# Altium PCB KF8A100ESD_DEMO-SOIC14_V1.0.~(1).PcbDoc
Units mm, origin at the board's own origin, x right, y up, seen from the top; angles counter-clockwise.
Board outline 54 x 31.99 mm, 2 copper layers (Top Layer, Bottom Layer); 38 components, 27 nets, 94 pads, 10 vias.
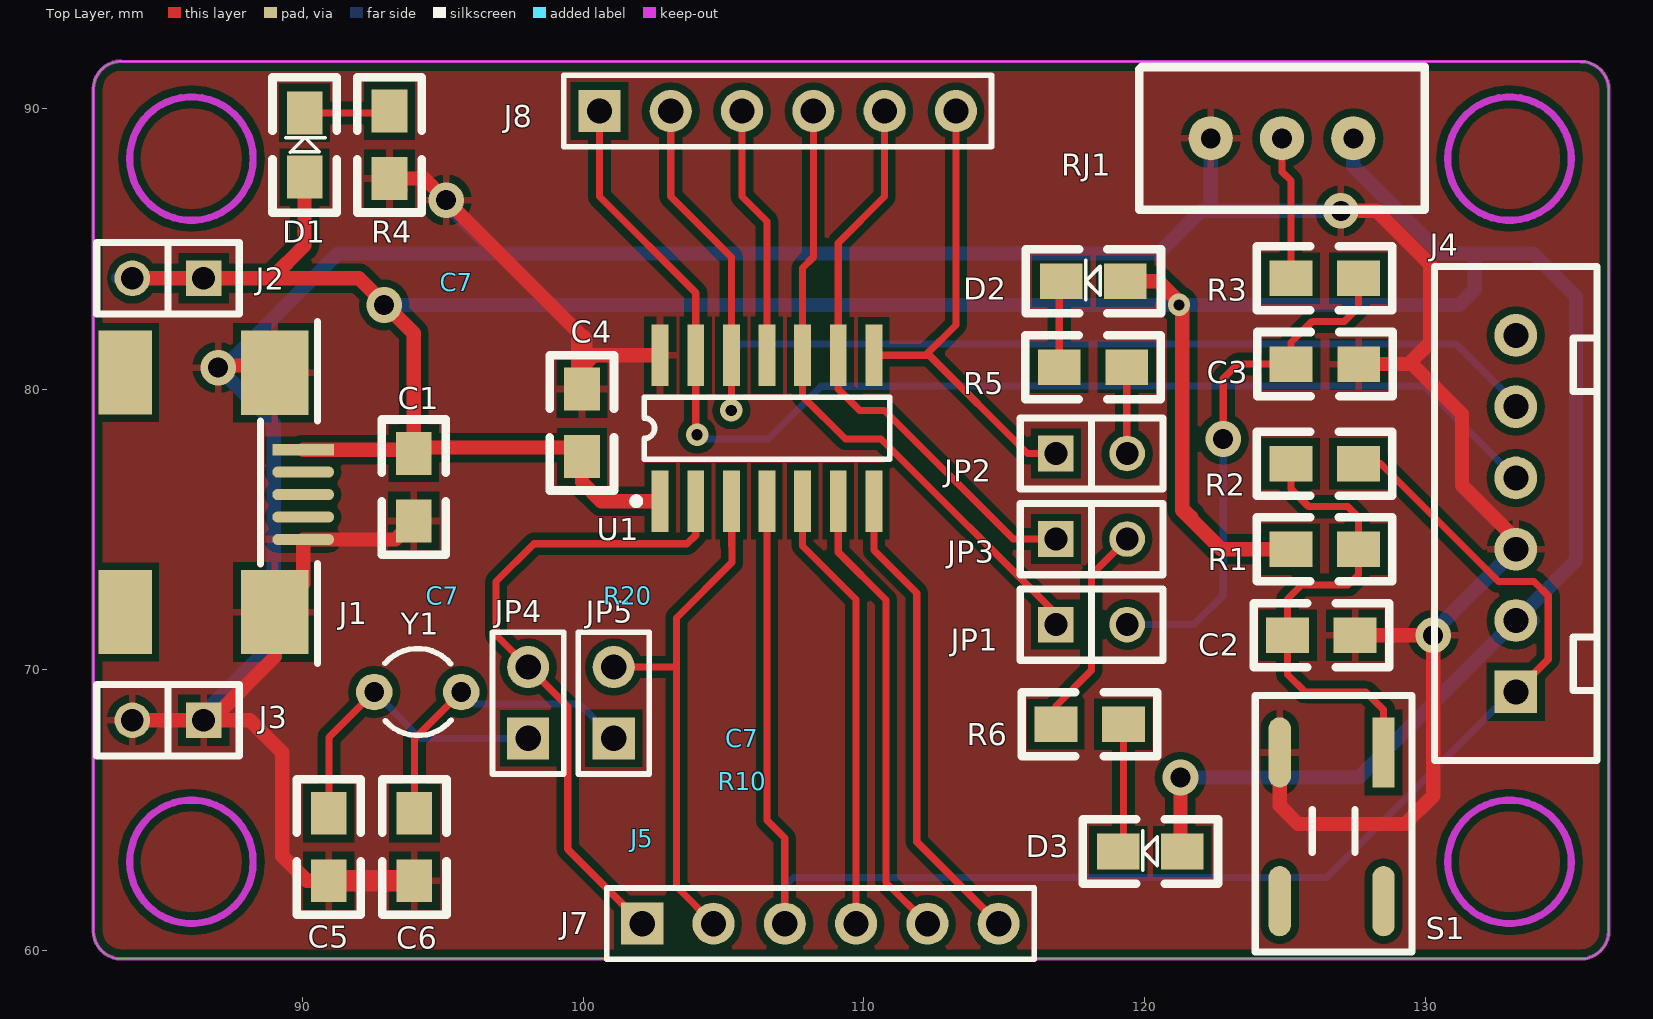
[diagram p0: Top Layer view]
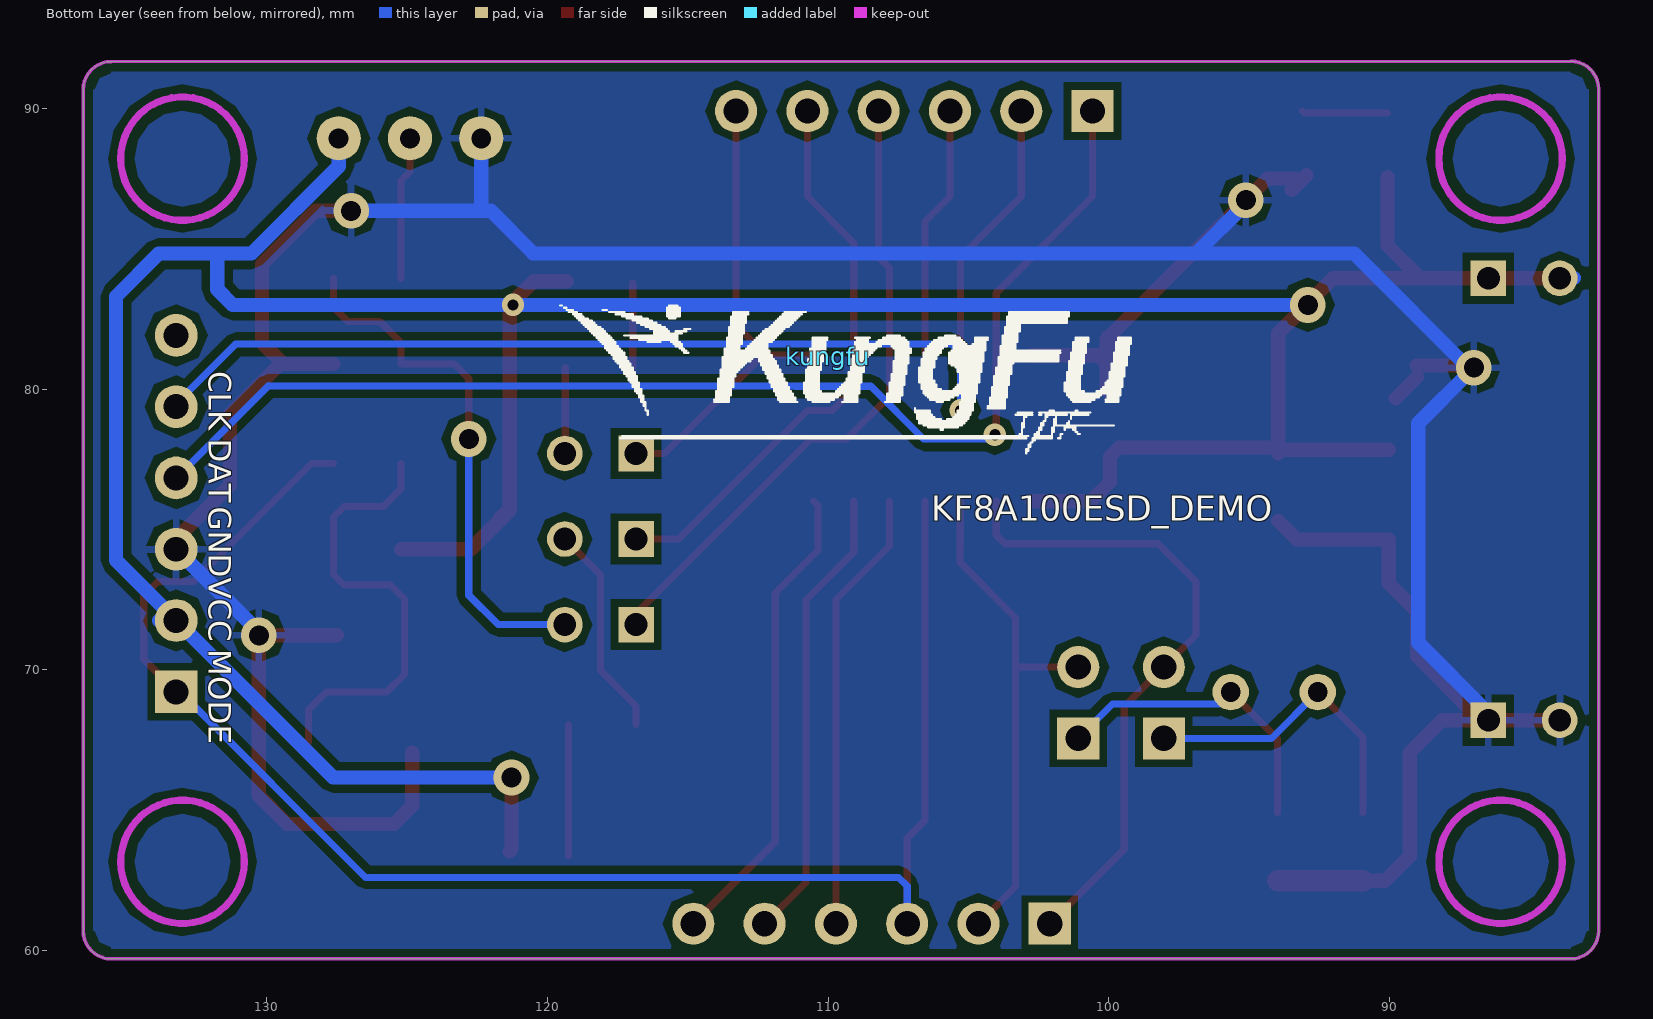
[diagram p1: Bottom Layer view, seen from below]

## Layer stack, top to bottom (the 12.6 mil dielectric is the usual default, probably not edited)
Top Solder: solder mask 0.0102, Solder Resist, Dk 3.5
Top Layer: signal copper 0.0356
Dielectric1: dielectric 0.32, FR-4, Dk 4.8
Bottom Layer: signal copper 0.0356
Bottom Solder: solder mask 0.0102, Solder Resist, Dk 3.5

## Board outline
82.55,60.706 ccw(c83.55,60.706) 83.55,59.706 135.55,59.706 ccw(c135.55,60.706) 136.55,60.706 136.55,90.678 ccw(c135.55,90.678) 135.55,91.678 83.55,91.694 ccw(c83.55,90.694) 82.55,90.694

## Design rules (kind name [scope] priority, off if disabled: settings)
Clearance [All] p1: gap=0.27
ComponentClearance [All] p1: gap=0 collisioncheckmode=3 verticalgap=0.254 showdistances=FALSE
FabricationTestPointUsage TestPointUsage [All] p1: valid=0 allowmultiple=FALSE
FabricationTestpoint Testpoint [All] p1: side=3 testpointundercomponent=TRUE minsize=1.016 maxsize=2.54 preferedsize=1.524 minholesize=0 maxholesize=1.016 preferedholesize=0.813 testpointgrid=0.025 allowsidetop=TRUE allowsidebottom=TRUE usegrid=TRUE gridtolerance=0
PolygonConnect [All] p1: connectstyle=Relief reliefconductorwidth=0.254 reliefentries=4 polygonreliefangle="90 Angle" airgapwidth=0.254
RoutingVias [All] p1: holewidth=0.711 width=1.27 viastyle="Through Hole" minholewidth=0.3 minwidth=0.6 maxholewidth=0.711 maxwidth=1.5
SilkToSolderMaskClearance SilkscreenOverComponentPads [IsPad] p1: minsilkscreentomaskgap=0.254 clearancetoexposedcopper=TRUE
SolderMaskExpansion [All] p1: expansion=0.102
UnpouredPolygon [All] p1: allowunpoured=FALSE
Width [InNet('GND')or InNet('VCC')] p1: maxlimit=0.762 minlimit=0.254 preferedwidth=0.254
25 further rules are at their usual default settings.

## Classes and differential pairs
component class KF8F3130-SOIC14: C1 C2 C3 C4 C5 C6 C7 D1 D2 J1 J2 J3 J4 J5 J6 J7 J8 JP1 JP2 JP3 JP4 JP5 R1 R2 R3 R4 R5 R6 RJ1 S1 U1 Y1

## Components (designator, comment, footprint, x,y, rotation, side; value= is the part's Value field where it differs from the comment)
C1 "105" 0805#1 93.98,77.724 r270 top
C2 "105" 0805#1 125.095,71.247 r0 top
C3 "103" 0805#1 125.221,80.909 r0 top
C4 "104" 0805#1 99.949,77.597 r90 top
C5 "" 0805#1 90.932,62.484 r90 top
C6 "" 0805#1 93.98,62.484 r90 top
C7 "Comment" 0603 105.664,67.564 r180 top
C7 "Comment" 0805#2 94.996,72.644 r180 top
C7 "105" 0805#2 95.504,83.82 r0 top
D1 "LED" LED0805 90.043,87.503 r90 top
D2 "LED" LED0805 119.38,83.82 r180 top
D3 "LED" LED0805 121.412,63.5 r180 top
J1 "Mini-IN" "MINI B USB" 90.035,74.653 r90 top
J2 "CON2" SIP2 86.487,83.947 r180 top
J3 "CON2" SIP2 86.487,68.199 r180 top
J4 "CON6" ICSP887 133.223,69.215 r90 top
J5 "Header 6" HDR1X6#1 102.108,64.008 r0 top
J6 "Header 6" HDR1X6#1 100.584,86.868 r0 top
J7 "Header 6" HDR1X6#2 102.108,60.96 r0 top
J8 "Header 6" HDR1X6#2 100.584,89.916 r0 top
JP1 "CON1X2" SIP2 116.84,71.628 r0 top
JP2 "CON1X2" SIP2 116.84,77.724 r0 top
JP3 "CON1X2" SIP2 116.84,74.676 r0 top
JP4 "" HDR1X3 98.044,67.564 r90 top
JP5 "" HDR1X3 101.092,67.564 r90 top
kungfu "Comment" KUNGFU 110.007,81.178 r180 bottom locked
R1 "30K" 0805#1 127.635,74.295 r180 top
R2 "1k" 0805#1 127.635,77.343 r180 top
R3 "1K" 0805#1 127.635,83.947 r180 top
R4 "330" 0805#1 93.091,87.503 r90 top
R5 "330" 0805#1 119.38,80.772 r180 top
R6 "330" 0805#1 116.84,68.072 r0 top
R10 "Comment" 0603 105.664,66.04 r180 top
R20 "Comment" 0805#2 101.6,72.644 r180 top
RJ1 "10K" VR5H 127.508,88.9 r180 top
S1 "" SW_SOP 128.524,67.056 r270 top
U1 "KF8F3132-SOIC20" SO14 106.553,78.613 r0 top
Y1 "32.768kHz" BCY-W2/D3.1 94.107,69.215 r90 top

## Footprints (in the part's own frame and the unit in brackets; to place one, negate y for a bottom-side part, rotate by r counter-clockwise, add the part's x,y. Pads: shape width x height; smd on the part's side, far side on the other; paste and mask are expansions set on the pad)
0603 [mm] "Chip Capacitor; Body 1.6 x 0.8 mm (LxW typ)"
0805#1 [mil]
  rect 60x50 smd: 1(0.31,-0.41) 2(95.03,-0.41)
  silkscreen extent -47,-45 143,45
0805#2 [mil]
BCY-W2/D3.1 [mm] "Crystal, Thru-Hole; 2 Leads; Body 3.1 x 8.2 mm (Dia.xH)"
  round 1.3 hole 0.7: 1(0,1.55) 2(0,-1.55)
  silkscreen extent -1.55,-1.19 1.55,1.17
HDR1X3 [mm] "Connector; Header; 3 Position"
  rect 1.5x1.5 hole 0.9: 1(0,0)
  round 1.5 hole 0.9: 2(2.54,0)
  silkscreen extent -1.27,-1.27 3.78,1.27
HDR1X6#1 [mm] "Connector; Header; 6 Position"
HDR1X6#2 [mm] "Connector; Header; 6 Position"
  rect 1.5x1.5 hole 0.9: 1(0,0)
  round 1.5 hole 0.9: 2(2.54,0) 3(5.08,0) 4(7.62,0) 5(10.16,0) 6(12.7,0)
  silkscreen extent -1.27,-1.27 13.97,1.27
ICSP887 [mil]
  rect 60x60 hole 35: 1(0.31,-0.41)
  round 60 hole 35: 2(100.31,-0.41) 3(200.31,-0.41) 4(300.31,-0.41) 5(400.31,-0.41) 6(500.31,-0.41)
  silkscreen extent -96,-115 597,114
KUNGFU [mm]
  silkscreen extent -9.55,-3.45 10.79,1.8
LED0805 [mil]
  rect 60x50 smd: A(2.31,-1.34) K(92.31,-1.34)
  silkscreen extent -48,-46 142,44
"MINI B USB" [mm]
  oval 0.4x2.2 smd: 1(-0.002,0.008) 2(0.798,0.008) 3(1.598,0.008) 4(2.398,0.008)
  rect 0.4x2.2 smd: 5(3.198,0.008)
  rect 3x2.4 smd: A1(-2.59,1.024) A1(5.938,1.024)
  rect 3x1.9 smd: A1(-2.587,6.348) A1(5.947,6.348)
  silkscreen extent -4.42,-0.5 7.77,1.53
SIP2 [mil]
  rect 50x50 hole 32: 1(0.31,-0.41)
  round 50 hole 32: 2(100.31,-0.41)
  silkscreen extent -50,-50 150,50
SO14 [mm] "Small Outline; 14 Leads; Body Width 3.9 mm; Pitch 1.27 mm"
  rect 0.6x2.2 smd: 1(-3.81,-2.6) 2(-2.54,-2.6) 3(-1.27,-2.6) 4(0,-2.6) 5(1.27,-2.6) 6(2.54,-2.6) 7(3.81,-2.6) 8(3.81,2.6) 9(2.54,2.6) 10(1.27,2.6) 11(0,2.6) 12(-1.27,2.6) 13(-2.54,2.6) 14(-3.81,2.6)
  silkscreen extent -4.78,-2.72 4.37,1.1
SW_SOP [mm]
  rect 2.5x0.8 smd: 1(-0.006,-0.003)
  oval 2.5x0.8 smd: 2(-0.006,-3.703) 3(5.294,-3.703) 4(5.294,-0.003)
  silkscreen extent -2.04,-4.57 7.11,1.01
VR5H [mil]
  round 62 hole 28: 1(2.5,-1.8) 2(202.5,-1.8) 3(102.5,-1.8)
  silkscreen extent -97,-102 303,98

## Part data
C1 C2 C3 C4 C5 C6 C7: library part CAP, "Capacitor"
J1: library part USB-5, "USB 1.1, Right Angle, Thru-Hole, Reverse Type, Receptacle, 4 Position, Black"
J2 J3 J4: "Connector"
J5 J7: library part "Header 9", "Header, 9-Pin"
J6 J8: "Header, 6-Pin"
JP1 JP2 JP3: "J?"
JP4 JP5: library part "Header 3", "Header, 3-Pin"
R1 R2 R3 R4 R5 R6: library part RES2
RJ1: library part POT2, "Potentiometer"
S1: library part KEY_X
U1: library part KF8F3130-SOIC14
Y1: library part XTAL, "Crystal Oscillator"

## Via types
v1: diameter 1.27, hole 0.711, Top Layer to Bottom Layer, tented both sides, 7 vias
v2: diameter 0.8, hole 0.4, Top Layer to Bottom Layer, tented both sides, 3 vias

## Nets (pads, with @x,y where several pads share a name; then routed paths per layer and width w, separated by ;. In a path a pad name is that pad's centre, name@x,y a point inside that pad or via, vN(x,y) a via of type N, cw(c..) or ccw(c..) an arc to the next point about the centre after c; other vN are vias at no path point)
GND: C1.2 C2.2 C3.2 C4.2 C5.1 C6.1 J1.1 J1.A1@89.01,72.063 J1.A1@89.01,80.591 J3.1 J3.2 J4.3 R4.1 RJ1.2 S1.2 U1.14 | length 145.8
  Top Layer w0.508: J3.2@83.703,68.209 88.128,68.209 89.281,67.056 89.281,63.373 90.162,62.492 C5.1 ; J3.1@86.751,68.209 89.019,70.477 J1.A1@89.019,71.913 ; v1(86.995,80.772) 87.071,80.848 J1.A1@89.027,80.848 ; J1.A1@89.01,72.063 90.026,73.079 J1.1 93.31,74.651 C1.2 ; J1.A1@89.019,80.441 J1.A1@89.789,79.671 ; R4.1@92.964,87.63 R4.1@93.482,87.112 ; R4.1@93.353,87.511 94.353,87.511 100,81.864 ; C4.2 99.959,80.782 100.39,81.213 U1.14 ; S1.2 124.821,65.171 125.476,64.516 129.286,64.516 130.292,65.522 v1(130.292,71.237) C2.2 ; v1(127,86.36) 128.27,86.36 130.175,84.455 130.175,81.661 129.413,80.899 ; C3.2 129.54,80.899 131.318,79.121 131.318,76.581 133.233,74.666 J4.3
  Top Layer w0.762: C5.1 C6.1 ; C4.2 99.959,81.768
  Bottom Layer w0.508: J3.1 86.479,68.471 88.976,70.968 88.976,78.791 v1@87.097,80.67 ; v1@86.817,80.62 87.046,80.62 91.262,84.836 120.523,84.836 120.523,84.861 122.022,86.36 v1(127,86.36) ; v1(95.123,86.741) 95.123,86.614 96.901,84.836 ; 122.364,86.36 RJ1.2 ; v1(130.292,71.237) 130.292,71.361 J4.3
NetC2_1: C2.1 R1.1 R2.2 S1.1 | length 16.4
  Top Layer w0.254: R2.2 125.221,76.455 125.857,75.819 127.254,75.819 127.627,75.446 127.627,73.398 127.254,73.025 125.603,73.025 125.103,72.525 125.103,69.842 125.73,69.215 127.889,69.215 128.521,68.583 S1.1@128.521,67.44
NetC3_1: C3.1 JP1.2 R3.1 | length 19
  Top Layer w0.254: v1(122.809,78.232) 122.809,80.391 123.317,80.899 C3.1 125.229,81.668 125.984,82.423 127.127,82.423 127.627,82.923 R3.1
  Bottom Layer w0.254: JP1.2@119.405,71.635 JP1.2 121.762,71.618 122.809,72.665 v1(122.809,78.232)
NetC5_2: C5.2 JP4.1 Y1.1 | length 11.2
  Top Layer w0.254: C5.2 90.942,67.6 Y1.1
  Bottom Layer w0.254: Y1.1 94.208,67.564 JP4.1
NetC6_2: C6.2 JP5.1 Y1.2 | length 11.4
  Top Layer w0.254: C6.2 93.99,67.548 Y1.2
  Bottom Layer w0.254: Y1.2 96.063,69.215 96.063,68.783 99.873,68.783 JP5.1
NetD1_K: D1.K R4.2 | length 3.1
  Top Layer w0.254: D1.K 93.032,89.848 R4.2
NetD2_K: D2.K R5.2 | length 3
  Top Layer w0.254: R5.2 D2.K@116.966,83.785
NetD3_K: D3.K R6.2 | length 7.6
  Top Layer w0.254: D3.K@119.253,63.373 R6.2@119.253,67.945 ; 119.254,65.024 R6.2
NetJP2_2: JP2.2 R5.1 | length 3.1
  Top Layer w0.254: R5.1 119.372,77.729 JP2.2
NetJP3_2: JP3.2 R6.1 | length 7.7
  Top Layer w0.254: R6.1 116.848,68.715 118.11,69.977 118.11,73.388 JP3.2
NetR3_2: R3.2 RJ1.3 | length 5.1
  Top Layer w0.254: RJ1.3 124.904,87.753 125.221,87.437 R3.2
P00: J4.4 J8.1 U1.13 | length 45.3
  Top Layer w0.254: J8.1 100.584,86.868 104.013,83.439 104.013,78.613 v2(104.064,78.384)
  Bottom Layer w0.254: v2(104.064,78.384) 103.886,78.232 106.604,78.232 108.48,80.108 111.188,80.108 ; 110.775,80.108 111.188,80.108 ; J4.4@133.233,77.079 J4.4 129.95,80.126 111.188,80.108
P01: J4.5 J8.2 U1.12 | length 42.9
  Top Layer w0.254: J8.2 103.124,86.868 105.283,84.709 U1.12 ; v2(105.283,79.248) 105.283,80.899 U1.12@105.41,81.026
  Bottom Layer w0.254: v2(105.283,79.248) 105.283,80.67 105.308,80.696 105.308,81.305 105.613,81.61 131.115,81.61 133.233,79.492 J4.5 J4.5@132.834,79.383
P02: J8.3 U1.11 | length 9.1
  Top Layer w0.254: J8.3 105.664,86.868 106.553,85.979 U1.11
P03: J4.1 J7.3 R2.1 U1.4 | length 58.2
  Top Layer w0.254: U1.4 106.553,64.643 107.188,64.008 J7.3 ; R2.1 128.412,77.353 132.613,73.152 133.883,73.152 134.391,72.644 134.391,70.381 J4.1
  Bottom Layer w0.254: J7.3 107.188,62.306 107.493,62.611 126.492,62.611 133.104,69.223 J4.1
P04: 
P05: 
P10: J8.4 JP1.1 U1.10 | length 22.9
  Top Layer w0.254: J8.4 108.204,84.709 107.823,84.328 107.823,79.756 109.347,78.232 110.617,78.232 116.848,72.001 JP1.1
P10.: 
P11: J8.5 JP3.1 U1.9 | length 20.6
  Top Layer w0.254: J8.5 110.744,86.868 109.093,85.217 109.093,80.01 109.855,79.248 110.744,79.248 115.326,74.666 JP3.1
P12: J8.6 JP2.1 U1.8 | length 17.5
  Top Layer w0.254: U1.8@110.363,80.823 U1.8 112.335,81.213 115.834,77.714 JP2.1 ; 112.201,81.213 113.284,82.296 113.284,86.868 J8.6
P20: J7.4 U1.5 | length 15.8
  Top Layer w0.254: U1.5 107.823,74.422 109.728,72.517 J7.4
P21: J7.5 U1.6 | length 16.4
  Top Layer w0.254: U1.6 109.093,74.193 110.795,72.492 110.795,62.433 J7.5
P22: J7.6 U1.7 | length 17
  Top Layer w0.254: U1.7@110.525,76.013 110.363,75.851 110.363,74.27 111.887,72.746 111.887,63.881 J7.6
PP04: J7.2 JP5.2 U1.3 | length 20.2
  Top Layer w0.254: JP5.2 103.302,70.104 103.327,70.079 ; J7.2 103.327,62.281 103.327,71.857 105.308,73.838 U1.3@105.308,75.997 ; 105.283,74.422 U1.3
PP05: J7.1 JP4.2 U1.2 | length 23.4
  Top Layer w0.254: J7.1 99.453,63.615 99.453,68.695 JP4.2 96.901,71.247 96.901,73.152 98.247,74.498 103.708,74.498 104.013,74.803 U1.2
VCC: C1.1 C4.1 D1.A D2.A D3.A J1.5 J2.1 J2.2 J4.2 R1.2 RJ1.1 U1.1 | length 131.4
  Top Layer w0.254: D2.A D2.A@119.321,83.947
  Top Layer w0.508: J2.2@83.881,83.957 92.014,83.957 93.97,82.002 C1.1 93.835,77.851 J1.5 ; 88.91,83.957 90.077,85.124 D1.A ; C1.1@93.97,77.927 99.637,77.927 C4.1 99.959,76.698 100.644,76.013 U1.1 ; D2.A 120.499,83.854 121.353,82.999 121.353,75.751 121.666,75.438 ; v1(121.285,66.167) 121.285,63.602 D3.A ; 121.353,75.692 122.74,74.305 R1.2
  Bottom Layer w0.254: J4.2 134.391,72.921
  Bottom Layer w0.508: J2.2@83.431,83.968 J2.2@83.939,83.968 ; v1(92.913,83.007) 131.216,83.007 131.775,83.566 131.775,84.836 ; v1(121.285,66.167) 127.638,66.167 135.382,73.911 135.382,83.312 133.858,84.836 130.556,84.836 127.444,87.948 RJ1.1 ; RJ1.1@127.381,89.154 RJ1.1@127.444,89.091 ; J4.2 J4.2@133.85,71.763
  other v2: 121.234,83.007
pads on no net: J1.2 J1.3 J1.4 J1.A1@83.686,72.066 J1.A1@83.686,80.6 J4.6 S1.3 S1.4

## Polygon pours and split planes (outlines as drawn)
GND on Top Layer "Top Layer-GND" (solid, pour order 1000): 83.561,91.766 83.155,91.766 82.926,91.537 82.647,91.258 82.647,60.422 82.774,60.295 83.18,59.889 135.682,59.889 135.91,60.118 136.139,60.346 136.368,60.575 136.368,90.826 136.114,91.08 136.114,91.461 83.536,91.461 83.536,91.817
GND on Bottom Layer "Bottom Layer-GND" (solid, pour order 1001): 83.397,91.711 135.569,91.711 135.95,91.33 136.407,91.33 136.407,91.102 136.585,90.924 136.585,60.673 136.432,60.52 136.305,60.393 136.153,60.241 135.848,59.936 83.169,59.936 82.915,60.19 82.915,60.444 82.762,60.596 82.762,89.756 82.61,89.908 82.61,90.721 82.711,90.822 82.711,91.051 82.991,91.33 83.092,91.432 83.27,91.432 83.423,91.584

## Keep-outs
Keep-Out Layer:
  circle w0.254: c86.045,63.163 r2.2
  circle w0.254: c133.01,63.163 r2.2
  circle w0.254: c133.01,88.221 r2.2
  circle w0.254: c86.045,88.221 r2.2
  lines w0.127: 82.55,60.706 ccw(c83.55,60.706) 83.55,59.706 135.55,59.706 ccw(c135.55,60.706) 136.55,60.706 136.55,90.678 ccw(c135.55,90.678) 135.55,91.678 83.55,91.694 ccw(c83.55,90.694) 82.55,90.694 82.55,60.706

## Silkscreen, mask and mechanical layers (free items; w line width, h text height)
Bottom Overlay:
  text "CLK" at 132.08,80.645 h0.8 r90
  text "DAT" at 132.08,78.232 h0.8 r90
  text "GND" at 132.08,75.819 h0.8 r90
  text "KF8A100ESD_DEMO" at 106.324,75.006 h1.52
  text "VCC" at 132.08,73.279 h0.8 r90
  text "MODE" at 132.08,70.739 h0.8 r90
